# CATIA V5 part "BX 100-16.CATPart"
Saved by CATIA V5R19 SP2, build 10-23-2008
Part number: BX 100-16
Bounding box of the stored display mesh (mm): x -18.951 to 18.951, y -18.952 to 18.952, z 0 to 100
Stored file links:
  C:\Users\Bora\Desktop\3D Katı model\BX serisi\BX 100\BX 100-16.CATPart
  C:\Program Files\Dassault Systemes\B19\intel_a\reffiles\standard\MetricThickPitch.txt
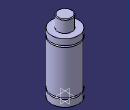
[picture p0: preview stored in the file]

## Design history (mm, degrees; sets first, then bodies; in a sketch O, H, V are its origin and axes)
Body1 (main body)
  Sketch1 on yz-plane, origin (0, 0, 0), H (0, 1, 0), V (0, 0, 1)
    point P2 (19, 74.5)
    point P4 (10, 99)
    point P6 (10, 99)
    point P8 (19, 74.5)
    point P9 (19, 72.5)
    point P10 (19, 72.5)
    point P11 (19, 11.5)
    point P12 (19, 11.5)
    point P13 (19, 9.5)
    point P14 (19, 9.5)
    line L1 (19, 83) -> (19, 74.5)
    line L2 (10, 99) -> (10, 83)
    arc A1 centre (9, 99) radius 1 from (10, 99) to (9, 100) ccw
    arc A2 centre (19, 73.5) radius 1 from (19, 74.5) to (19, 72.5) ccw
    line L3 (19, 72.5) -> (19, 11.5)
    arc A3 centre (19, 10.5) radius 1 from (19, 11.5) to (19, 9.5) ccw
    line L4 (19, 9.5) -> (19, 0)
    line L5 (0, 100) -> (9, 100)
    line L6 (10, 83) -> (19, 83)
    line L7 (0, 0) -> (19, 0)
    horizontal: L5 H, L6 H, L7 H
    coincidence: P2 P8, P4 P6, P9 P10, P11 P12, P13 P14
  Shaft1: profile Sketch1, axis Sketch1.V, angle 360
  Sketch2 on face of Shaft1 from Sketch1.L7, origin (0, 0, 0), H (1, 0, 0), V (0, -1, 0)
    point P1 (9, 0)
    distance P1 V = 9
  Hole1: placed by Sketch2, at (9, 0, 0) direction (0, 0, 1), diameter 4.917, depth 6, threaded "M6", thread diameter 6, thread depth 6, pitch 1
  Sketch3 on face of Shaft1 from Sketch1.L7, origin (0, 0, 0), H (1, 0, 0), V (0, -1, 0)
    point P1 (-9, 0)
    distance P1 V = 9
  Hole2: placed by Sketch3, at (-9, 0, 0) direction (0, 0, 1), diameter 4.917, depth 6, threaded "M6", thread diameter 6, thread depth 6, pitch 1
